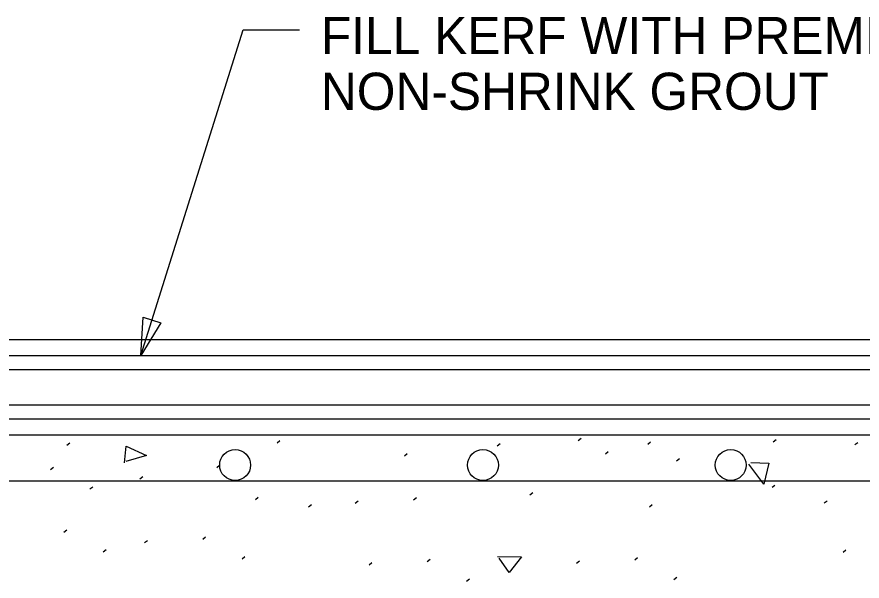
# Model space of a CAD drawing. Extents: x 3239 to 4230, y -4276 to -2494.
# Drawn here: x 3469.7 to 3537.9, y -3412 to -3366.5 of the extents above; entities that cross this region are included whole.
import ezdxf

# ---------------------------------------------------------------- set-up
doc = ezdxf.new("R2010")
doc.units = 0
doc.layers.add('2', color=7, linetype='Continuous')

msp = doc.modelspace()

# ---------------------------------------------------------------- linework, layer by layer
at = {"layer": '2'}
for p, q in [((3432.777, -3392.515), (3671.69, -3392.515)), ((3442.858, -3393.818), (3574.241, -3393.818)), ((3435.277, -3394.94), (3574.241, -3394.94)), ((3435.277, -3397.79), (3574.241, -3397.79)), ((3442.858, -3398.912), (3574.241, -3398.912)), ((3407.277, -3400.215), (3579.7, -3400.215)), ((3515.034, -3400.671), (3515.267, -3400.485)), ((3530.77, -3400.769), (3531.003, -3400.583)), ((3473.75, -3401.043), (3473.983, -3400.857)), ((3490.723, -3400.869), (3490.956, -3400.683)), ((3508.487, -3401.114), (3508.72, -3400.928)), ((3520.635, -3400.979), (3520.868, -3400.792)), ((3537.355, -3401.009), (3537.588, -3400.822)), ((3500.997, -3401.917), (3501.23, -3401.731)), ((3517.224, -3401.752), (3517.457, -3401.566)), ((3485.854, -3402.849), (3486.087, -3402.663)), ((3522.961, -3402.316), (3523.194, -3402.129)), ((3472.445, -3403), (3472.678, -3402.814)), ((3381.498, -3403.936), (3591.059, -3403.936)), ((3479.644, -3403.769), (3479.877, -3403.583)), ((3475.614, -3404.584), (3475.847, -3404.398)), ((3530.677, -3404.45), (3530.91, -3404.264)), ((3488.975, -3405.427), (3489.208, -3405.24)), ((3501.74, -3405.456), (3501.973, -3405.27)), ((3511.12, -3405.052), (3511.353, -3404.865)), ((3493.262, -3406.018), (3493.495, -3405.831)), ((3497.037, -3405.738), (3497.27, -3405.552)), ((3520.775, -3406.011), (3521.008, -3405.825)), ((3534.882, -3405.715), (3535.115, -3405.528)), ((3473.516, -3408.077), (3473.749, -3407.891)), ((3480.02, -3408.913), (3480.253, -3408.727)), ((3484.723, -3408.631), (3484.956, -3408.444)), ((3476.684, -3409.661), (3476.917, -3409.475)), ((3536.402, -3409.678), (3536.635, -3409.492)), ((3487.892, -3410.215), (3488.125, -3410.029)), ((3519.59, -3410.292), (3519.823, -3410.106)), ((3498.145, -3410.713), (3498.378, -3410.526)), ((3502.849, -3410.431), (3503.082, -3410.244)), ((3514.887, -3410.574), (3515.12, -3410.388)), ((3506.017, -3412.015), (3506.25, -3411.828)), ((3522.759, -3411.876), (3522.992, -3411.69))]:
    msp.add_line(p, q, dxfattribs=at)
for points in [[(3479.72, -3393.818), (3487.997, -3367.54), (3492.536, -3367.54)], [(3478.409, -3402.488), (3478.549, -3401.136), (3480.18, -3401.882), (3478.526, -3402.371)], [(3528.948, -3402.438), (3530.416, -3402.508), (3530.02, -3404.209), (3528.809, -3402.578)], [(3508.509, -3410.038), (3510.442, -3410.061), (3509.464, -3411.319), (3508.649, -3410.178)]]:
    msp.add_lwpolyline(points, dxfattribs=at)
msp.add_lwpolyline([(3481.336, -3391.182), (3479.72, -3393.818), (3479.906, -3390.731)], close=True, dxfattribs=at)
for centre in [(3487.337, -3402.653), (3507.337, -3402.653), (3527.337, -3402.653)]:
    msp.add_circle(centre, 1.247, dxfattribs=at)

# ---------------------------------------------------------------- texts
for s, p in [('FILL KERF WITH PREMIXED', (3494.258, -3369.5)), ('NON-SHRINK GROUT', (3494.258, -3374))]:
    msp.add_text(s, height=3, dxfattribs=at).set_placement(p)

doc.saveas('drawing.dxf')
